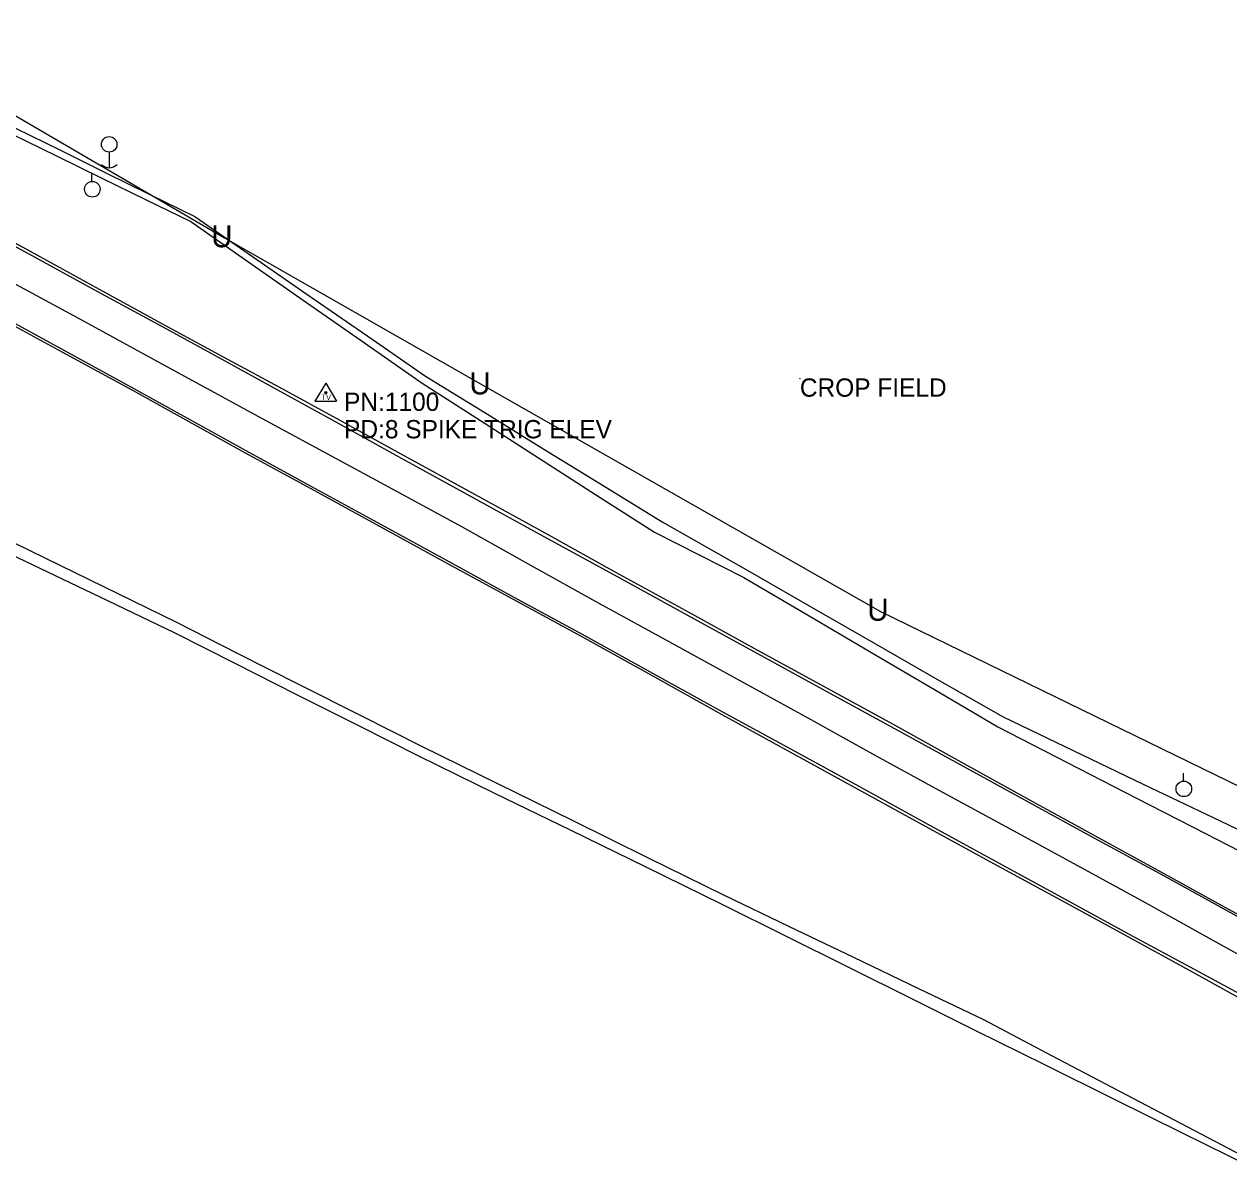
# Model space of a CAD drawing. Extents: x 1411444 to 1458157, y 300965 to 327300.
# Drawn here: x 1455288.2 to 1455617.6, y 302257.6 to 302570 of the extents above; entities that cross this region are included whole.
import ezdxf

# ---------------------------------------------------------------- set-up
doc = ezdxf.new("R2010")
doc.units = 0
for name, color, linetype in [('S_DITCHLINE', 7, 'Continuous'), ('S_EDGE_PAVEMENT', 7, 'Continuous'), ('S_MSC_PT_SYM', 7, 'Continuous'), ('S_PAVEMENT_CROWN', 7, 'Continuous'), ('S_SECONDARY_CTL', 7, 'Continuous'), ('S_SECONDARY_CTL_ANNOT', 7, 'Continuous'), ('S_SHOULDER', 7, 'Continuous'), ('S_SURVEY_TEXT_ANNOT', 7, 'Continuous'), ('S_UNDERGROUND_CABLE', 7, 'Continuous'), ('S_UTILITY_POLE', 7, 'Continuous'), ('S_UTL_PT_SYM', 7, 'Continuous')]:
    doc.layers.add(name, color=color, linetype=linetype)

msp = doc.modelspace()

# ---------------------------------------------------------------- linework, layer by layer
at = {"layer": 'S_DITCHLINE'}
for points in [[(1455285.89, 302541.52), (1455298.14, 302535.49), (1455310.39, 302529.45), (1455322.63, 302523.42), (1455334.88, 302517.39), (1455350.66, 302506.47), (1455366.44, 302495.56), (1455382.21, 302484.65), (1455397.99, 302473.74), (1455414.15, 302463.79), (1455430.31, 302453.83), (1455446.47, 302443.87), (1455462.63, 302433.92), (1455486.06, 302420.63), (1455503.5, 302410.62), (1455520.95, 302400.61), (1455538.39, 302390.6), (1455555.83, 302380.59), (1455574.99, 302371.43), (1455594.15, 302362.27), (1455613.31, 302353.1), (1455632.46, 302343.94)], [(1455284.79, 302540.02), (1455297.05, 302534.01), (1455309.31, 302528.01), (1455321.56, 302522), (1455333.82, 302515.99), (1455349.63, 302504.96), (1455365.45, 302493.92), (1455381.26, 302482.88), (1455397.08, 302471.85), (1455412.96, 302461.66), (1455428.84, 302451.47), (1455444.72, 302441.27), (1455460.59, 302431.08), (1455485, 302418.72), (1455502.36, 302408.5), (1455519.71, 302398.29), (1455537.07, 302388.08), (1455554.43, 302377.86), (1455573.35, 302368.14), (1455592.27, 302358.42), (1455611.19, 302348.7), (1455630.11, 302338.98)], [(1455269.97, 302435.76), (1455289.93, 302426), (1455309.9, 302416.24), (1455329.87, 302406.48), (1455346.66, 302397.99), (1455363.44, 302389.51), (1455380.23, 302381.02), (1455397.02, 302372.54), (1455417.62, 302362.4), (1455438.22, 302352.26), (1455458.81, 302342.12), (1455479.41, 302331.98), (1455497.17, 302323.45), (1455514.94, 302314.92), (1455532.7, 302306.39), (1455550.46, 302297.86), (1455569.05, 302288.09), (1455587.64, 302278.32), (1455606.23, 302268.54), (1455624.82, 302258.77)], [(1455268.1, 302432.98), (1455288.49, 302423.21), (1455308.88, 302413.44), (1455329.27, 302403.67), (1455346, 302395.22), (1455362.72, 302386.77), (1455379.45, 302378.33), (1455396.18, 302369.88), (1455416.84, 302359.79), (1455437.49, 302349.71), (1455458.15, 302339.62), (1455478.8, 302329.53), (1455496.18, 302320.87), (1455513.56, 302312.21), (1455530.94, 302303.55), (1455548.32, 302294.89), (1455567.15, 302285.57), (1455585.98, 302276.25), (1455604.8, 302266.93), (1455623.63, 302257.6)]]:
    msp.add_lwpolyline(points, dxfattribs=at)
at = {"layer": 'S_EDGE_PAVEMENT'}
for points in [[(1455269.97, 302517.78), (1455289.49, 302507.22), (1455308.31, 302496.94), (1455327.13, 302486.66), (1455342.3, 302478.36), (1455357.47, 302470.06), (1455374.06, 302460.87), (1455390.65, 302451.69), (1455411.11, 302440.5), (1455430.31, 302429.96), (1455449.52, 302419.43), (1455468.61, 302408.96), (1455487.7, 302398.49), (1455506.44, 302388.24), (1455525.19, 302377.98), (1455543.92, 302367.67), (1455562.66, 302357.36), (1455580.66, 302347.56), (1455598.66, 302337.77), (1455616.19, 302328.12), (1455633.72, 302318.47)], [(1455279.86, 302491.31), (1455299.05, 302480.83), (1455318.25, 302470.35), (1455333.53, 302461.9), (1455348.82, 302453.44), (1455365.8, 302444.15), (1455382.78, 302434.86), (1455403.51, 302423.54), (1455422.13, 302413.37), (1455440.75, 302403.19), (1455459.96, 302392.6), (1455479.16, 302382.01), (1455497.87, 302371.78), (1455516.59, 302361.56), (1455535.09, 302351.42), (1455553.58, 302341.29), (1455571.84, 302331.32), (1455590.09, 302321.35), (1455608.11, 302311.62), (1455626.14, 302301.9)]]:
    msp.add_lwpolyline(points, dxfattribs=at)
at = {"layer": 'S_MSC_PT_SYM'}
msp.add_lwpolyline([(1455500.29, 302473.14), (1455500.29, 302473.19), (1455500.29, 302473.14), (1455500.24, 302473.14), (1455500.29, 302473.14), (1455500.29, 302473.09), (1455500.29, 302473.14), (1455500.34, 302473.14)], dxfattribs=at)
at = {"layer": 'S_PAVEMENT_CROWN'}
msp.add_lwpolyline([(1455284.91, 302499.49), (1455303.9, 302489.15), (1455322.89, 302478.81), (1455338.11, 302470.47), (1455353.33, 302462.14), (1455369.98, 302453.13), (1455386.63, 302444.12), (1455408, 302432.53), (1455426.68, 302422.11), (1455445.36, 302411.7), (1455464.63, 302401.15), (1455483.9, 302390.6), (1455502.42, 302380.34), (1455520.94, 302370.08), (1455539.28, 302360.08), (1455557.62, 302350.09), (1455576.15, 302339.96), (1455594.68, 302329.84), (1455612.22, 302320.13), (1455629.76, 302310.42)], dxfattribs=at)
at = {"layer": 'S_SECONDARY_CTL'}
for p, q in [((1455370.7, 302471.87), (1455367.69, 302466.91)), ((1455370.7, 302471.87), (1455373.65, 302466.91)), ((1455367.69, 302466.91), (1455373.65, 302466.91))]:
    msp.add_line(p, q, dxfattribs=at)
for radius in [0.311, 0.183, 0.103]:
    msp.add_circle((1455370.7, 302469.26), radius, dxfattribs=at)
at = {"layer": 'S_SHOULDER'}
for points in [[(1455205.08, 302530.8), (1455223.9, 302520.82), (1455242.71, 302510.84), (1455261.16, 302500.79), (1455279.61, 302490.74), (1455298.71, 302480.31), (1455317.81, 302469.89), (1455333.22, 302461.35), (1455348.62, 302452.82), (1455365.59, 302443.57), (1455382.57, 302434.33), (1455402.96, 302423.1), (1455421.74, 302412.88), (1455440.52, 302402.66), (1455459.74, 302391.98), (1455478.96, 302381.3), (1455497.56, 302371.06), (1455516.17, 302360.82), (1455534.7, 302350.69), (1455553.24, 302340.56), (1455571.49, 302330.6), (1455589.75, 302320.65), (1455607.7, 302310.79), (1455625.65, 302300.93)], [(1455270.32, 302518.45), (1455289.88, 302507.91), (1455308.7, 302497.58), (1455327.53, 302487.24), (1455342.68, 302479.05), (1455357.83, 302470.86), (1455374.5, 302461.7), (1455391.18, 302452.55), (1455411.55, 302441.39), (1455430.73, 302430.8), (1455449.91, 302420.22), (1455468.9, 302409.78), (1455487.89, 302399.35), (1455506.75, 302389.02), (1455525.6, 302378.68), (1455544.32, 302368.3), (1455563.05, 302357.91), (1455580.99, 302348.09), (1455598.94, 302338.26), (1455616.47, 302328.64), (1455634, 302319.02)]]:
    msp.add_lwpolyline(points, dxfattribs=at)
at = {"layer": 'S_UNDERGROUND_CABLE'}
for p, q in [((1455242.98, 302570), (1455343.01, 302511.53)), ((1455343.01, 302511.53), (1455413.6, 302471.33)), ((1455413.6, 302471.33), (1455522.35, 302409.44)), ((1455522.35, 302409.44), (1455630.78, 302356.56))]:
    msp.add_line(p, q, dxfattribs=at)
at = {"layer": 'S_UTILITY_POLE'}
for p, q in [((1455311.49, 302534.94), (1455311.49, 302530.71)), ((1455306.75, 302527), (1455306.75, 302529.11)), ((1455605.12, 302363.08), (1455605.12, 302365.19))]:
    msp.add_line(p, q, dxfattribs=at)
for centre in [(1455311.48, 302537.12), (1455306.87, 302524.86), (1455605.25, 302360.94)]:
    msp.add_circle(centre, 2.13, dxfattribs=at)
msp.add_arc((1455311.49, 302533.82), 3.09, 226.3972, 313.6028, dxfattribs=at)

# ---------------------------------------------------------------- texts
at = {"layer": 'S_SECONDARY_CTL'}
msp.add_text('TV', height=1.5, rotation=360, dxfattribs=at).set_placement((1455369.5, 302467.24))
at = {"layer": 'S_SECONDARY_CTL_ANNOT'}
for s, p in [('PN:1100', (1455375.7, 302464.26)), ('PD:8 SPIKE TRIG ELEV', (1455375.7, 302456.76))]:
    msp.add_text(s, height=5, dxfattribs=at).set_placement(p)
at = {"layer": 'S_SURVEY_TEXT_ANNOT'}
msp.add_text('CROP FIELD', height=5, dxfattribs=at).set_placement((1455500.29, 302468.14))
at = {"layer": 'S_UTL_PT_SYM'}
for p in [(1455339.38, 302508.99), (1455409.97, 302468.78), (1455518.72, 302406.9)]:
    msp.add_text('U', height=6, rotation=360, dxfattribs=at).set_placement(p)

doc.saveas('drawing.dxf')
